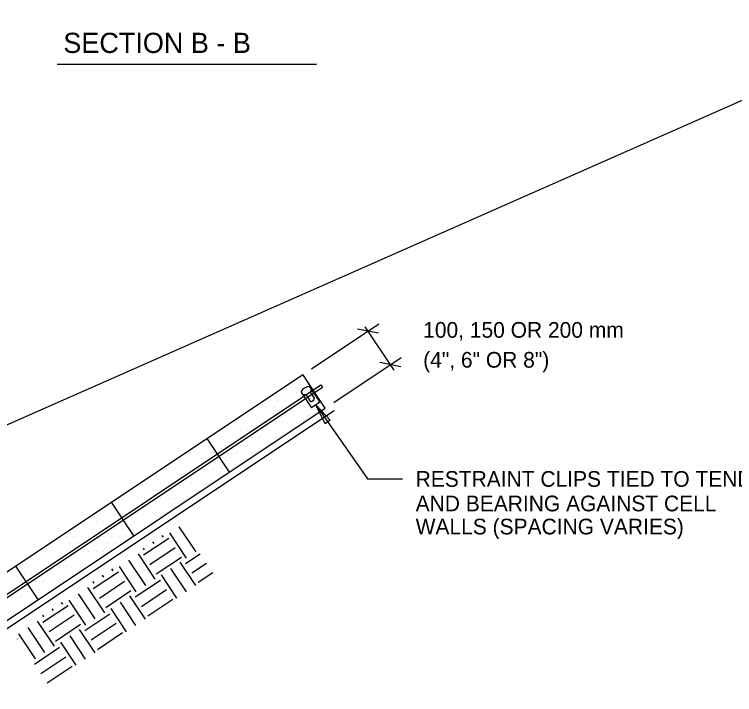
# Model space of a CAD drawing. Extents: x 638850 to 644908, y 297188 to 298900.
# Drawn here: x 641716.6 to 641845.1, y 297497.1 to 297618.5 of the extents above; entities that cross this region are included whole.
import ezdxf

# ---------------------------------------------------------------- set-up
doc = ezdxf.new("R2010")
doc.units = 0
for name, color, linetype in [('1', 7, 'Continuous'), ('12', 7, 'Continuous'), ('13', 7, 'Continuous'), ('3', 7, 'Continuous'), ('4', 7, 'Continuous'), ('5', 7, 'Continuous'), ('6', 7, 'Continuous'), ('7', 7, 'Continuous'), ('8', 7, 'Continuous')]:
    doc.layers.add(name, color=color, linetype=linetype)

msp = doc.modelspace()

# ---------------------------------------------------------------- linework, layer by layer
at = {"layer": '1'}
msp.add_line((644544.42, 298794.06), (640943.9, 297204.77), dxfattribs=at)
at = {"layer": '12'}
for p, q in [((641768.33, 297553.73), (641768.33, 297553.73)), ((641766.31, 297552.38), (641766.31, 297552.38)), ((641767.66, 297552.38), (641767.66, 297552.38)), ((641769.01, 297552.38), (641769.01, 297552.38)), ((641764.28, 297551.03), (641764.28, 297551.03)), ((641765.63, 297551.03), (641765.63, 297551.03)), ((641766.98, 297551.03), (641766.98, 297551.03)), ((641768.33, 297551.03), (641768.33, 297551.03)), ((641769.68, 297551.03), (641769.68, 297551.03)), ((641762.26, 297549.68), (641762.26, 297549.68)), ((641763.61, 297549.68), (641763.61, 297549.68)), ((641764.96, 297549.68), (641764.96, 297549.68)), ((641766.31, 297549.68), (641766.31, 297549.68)), ((641767.66, 297549.68), (641767.66, 297549.68)), ((641769.01, 297549.68), (641769.01, 297549.68)), ((641770.36, 297549.68), (641770.36, 297549.68)), ((641760.23, 297548.33), (641760.23, 297548.33)), ((641761.58, 297548.33), (641761.58, 297548.33)), ((641762.93, 297548.33), (641762.93, 297548.33)), ((641764.28, 297548.33), (641764.28, 297548.33)), ((641765.63, 297548.33), (641765.63, 297548.33)), ((641766.98, 297548.33), (641766.98, 297548.33)), ((641768.33, 297548.33), (641768.33, 297548.33)), ((641769.68, 297548.33), (641769.68, 297548.33)), ((641771.03, 297548.33), (641771.03, 297548.33)), ((641758.21, 297546.98), (641758.21, 297546.98)), ((641759.56, 297546.98), (641759.56, 297546.98)), ((641760.91, 297546.98), (641760.91, 297546.98)), ((641762.26, 297546.98), (641762.26, 297546.98)), ((641763.61, 297546.98), (641763.61, 297546.98)), ((641764.96, 297546.98), (641764.96, 297546.98)), ((641766.31, 297546.98), (641766.31, 297546.98)), ((641767.66, 297546.98), (641767.66, 297546.98)), ((641769.01, 297546.98), (641769.01, 297546.98)), ((641756.18, 297545.63), (641756.18, 297545.63)), ((641757.53, 297545.63), (641757.53, 297545.63)), ((641758.88, 297545.63), (641758.88, 297545.63)), ((641760.23, 297545.63), (641760.23, 297545.63)), ((641761.58, 297545.63), (641761.58, 297545.63)), ((641762.93, 297545.63), (641762.93, 297545.63)), ((641764.28, 297545.63), (641764.28, 297545.63)), ((641765.63, 297545.63), (641765.63, 297545.63)), ((641766.98, 297545.63), (641766.98, 297545.63)), ((641754.16, 297544.28), (641754.16, 297544.28)), ((641755.51, 297544.28), (641755.51, 297544.28)), ((641756.86, 297544.28), (641756.86, 297544.28)), ((641758.21, 297544.28), (641758.21, 297544.28)), ((641759.56, 297544.28), (641759.56, 297544.28)), ((641760.91, 297544.28), (641760.91, 297544.28)), ((641762.26, 297544.28), (641762.26, 297544.28)), ((641763.61, 297544.28), (641763.61, 297544.28)), ((641764.96, 297544.28), (641764.96, 297544.28)), ((641752.13, 297542.93), (641752.13, 297542.93)), ((641753.48, 297542.93), (641753.48, 297542.93)), ((641754.83, 297542.93), (641754.83, 297542.93)), ((641756.18, 297542.93), (641756.18, 297542.93)), ((641757.53, 297542.93), (641757.53, 297542.93)), ((641758.88, 297542.93), (641758.88, 297542.93)), ((641760.23, 297542.93), (641760.23, 297542.93)), ((641761.58, 297542.93), (641761.58, 297542.93)), ((641762.93, 297542.93), (641762.93, 297542.93)), ((641750.11, 297541.58), (641750.11, 297541.58)), ((641751.46, 297541.58), (641751.46, 297541.58)), ((641752.81, 297541.58), (641752.81, 297541.58)), ((641754.16, 297541.58), (641754.16, 297541.58)), ((641755.51, 297541.58), (641755.51, 297541.58)), ((641756.86, 297541.58), (641756.86, 297541.58)), ((641758.21, 297541.58), (641758.21, 297541.58)), ((641759.56, 297541.58), (641759.56, 297541.58)), ((641760.91, 297541.58), (641760.91, 297541.58)), ((641748.08, 297540.23), (641748.08, 297540.23)), ((641749.43, 297540.23), (641749.43, 297540.23)), ((641750.78, 297540.23), (641750.78, 297540.23)), ((641752.13, 297540.23), (641752.13, 297540.23)), ((641753.48, 297540.23), (641753.48, 297540.23)), ((641754.83, 297540.23), (641754.83, 297540.23)), ((641756.18, 297540.23), (641756.18, 297540.23)), ((641757.53, 297540.23), (641757.53, 297540.23)), ((641758.88, 297540.23), (641758.88, 297540.23)), ((641746.06, 297538.88), (641746.06, 297538.88)), ((641747.41, 297538.88), (641747.41, 297538.88)), ((641748.76, 297538.88), (641748.76, 297538.88)), ((641750.11, 297538.88), (641750.11, 297538.88)), ((641751.46, 297538.88), (641751.46, 297538.88)), ((641752.81, 297538.88), (641752.81, 297538.88)), ((641754.16, 297538.88), (641754.16, 297538.88)), ((641755.51, 297538.88), (641755.51, 297538.88)), ((641756.86, 297538.88), (641756.86, 297538.88)), ((641744.03, 297537.53), (641744.03, 297537.53)), ((641745.38, 297537.53), (641745.38, 297537.53)), ((641746.73, 297537.53), (641746.73, 297537.53)), ((641748.08, 297537.53), (641748.08, 297537.53)), ((641749.43, 297537.53), (641749.43, 297537.53)), ((641750.78, 297537.53), (641750.78, 297537.53)), ((641752.13, 297537.53), (641752.13, 297537.53)), ((641753.48, 297537.53), (641753.48, 297537.53)), ((641754.83, 297537.53), (641754.83, 297537.53)), ((641742.01, 297536.18), (641742.01, 297536.18)), ((641743.36, 297536.18), (641743.36, 297536.18)), ((641744.71, 297536.18), (641744.71, 297536.18)), ((641746.06, 297536.18), (641746.06, 297536.18)), ((641747.41, 297536.18), (641747.41, 297536.18)), ((641748.76, 297536.18), (641748.76, 297536.18)), ((641750.11, 297536.18), (641750.11, 297536.18)), ((641751.46, 297536.18), (641751.46, 297536.18)), ((641752.81, 297536.18), (641752.81, 297536.18)), ((641739.98, 297534.83), (641739.98, 297534.83)), ((641741.33, 297534.83), (641741.33, 297534.83)), ((641742.68, 297534.83), (641742.68, 297534.83)), ((641744.03, 297534.83), (641744.03, 297534.83)), ((641745.38, 297534.83), (641745.38, 297534.83)), ((641746.73, 297534.83), (641746.73, 297534.83)), ((641748.08, 297534.83), (641748.08, 297534.83)), ((641749.43, 297534.83), (641749.43, 297534.83)), ((641750.78, 297534.83), (641750.78, 297534.83)), ((641737.96, 297533.48), (641737.96, 297533.48)), ((641739.31, 297533.48), (641739.31, 297533.48)), ((641740.66, 297533.48), (641740.66, 297533.48)), ((641742.01, 297533.48), (641742.01, 297533.48)), ((641743.36, 297533.48), (641743.36, 297533.48)), ((641744.71, 297533.48), (641744.71, 297533.48)), ((641746.06, 297533.48), (641746.06, 297533.48)), ((641747.41, 297533.48), (641747.41, 297533.48)), ((641748.76, 297533.48), (641748.76, 297533.48)), ((641735.93, 297532.13), (641735.93, 297532.13)), ((641737.28, 297532.13), (641737.28, 297532.13)), ((641738.63, 297532.13), (641738.63, 297532.13)), ((641739.98, 297532.13), (641739.98, 297532.13)), ((641741.33, 297532.13), (641741.33, 297532.13)), ((641742.68, 297532.13), (641742.68, 297532.13)), ((641744.03, 297532.13), (641744.03, 297532.13)), ((641745.38, 297532.13), (641745.38, 297532.13)), ((641746.73, 297532.13), (641746.73, 297532.13)), ((641733.91, 297530.78), (641733.91, 297530.78)), ((641735.26, 297530.78), (641735.26, 297530.78)), ((641736.61, 297530.78), (641736.61, 297530.78)), ((641737.96, 297530.78), (641737.96, 297530.78)), ((641739.31, 297530.78), (641739.31, 297530.78)), ((641740.66, 297530.78), (641740.66, 297530.78)), ((641742.01, 297530.78), (641742.01, 297530.78)), ((641743.36, 297530.78), (641743.36, 297530.78)), ((641744.71, 297530.78), (641744.71, 297530.78)), ((641731.88, 297529.43), (641731.88, 297529.43)), ((641733.23, 297529.43), (641733.23, 297529.43)), ((641734.58, 297529.43), (641734.58, 297529.43)), ((641735.93, 297529.43), (641735.93, 297529.43)), ((641737.28, 297529.43), (641737.28, 297529.43)), ((641738.63, 297529.43), (641738.63, 297529.43)), ((641739.98, 297529.43), (641739.98, 297529.43)), ((641741.33, 297529.43), (641741.33, 297529.43)), ((641742.68, 297529.43), (641742.68, 297529.43)), ((641729.86, 297528.08), (641729.86, 297528.08)), ((641731.21, 297528.08), (641731.21, 297528.08)), ((641732.56, 297528.08), (641732.56, 297528.08)), ((641733.91, 297528.08), (641733.91, 297528.08)), ((641735.26, 297528.08), (641735.26, 297528.08)), ((641736.61, 297528.08), (641736.61, 297528.08)), ((641737.96, 297528.08), (641737.96, 297528.08)), ((641739.31, 297528.08), (641739.31, 297528.08)), ((641740.66, 297528.08), (641740.66, 297528.08)), ((641727.83, 297526.73), (641727.83, 297526.73)), ((641729.18, 297526.73), (641729.18, 297526.73)), ((641730.53, 297526.73), (641730.53, 297526.73)), ((641731.88, 297526.73), (641731.88, 297526.73)), ((641733.23, 297526.73), (641733.23, 297526.73)), ((641734.58, 297526.73), (641734.58, 297526.73)), ((641735.93, 297526.73), (641735.93, 297526.73)), ((641737.28, 297526.73), (641737.28, 297526.73)), ((641738.63, 297526.73), (641738.63, 297526.73)), ((641725.81, 297525.38), (641725.81, 297525.38)), ((641727.16, 297525.38), (641727.16, 297525.38)), ((641728.51, 297525.38), (641728.51, 297525.38)), ((641729.86, 297525.38), (641729.86, 297525.38)), ((641731.21, 297525.38), (641731.21, 297525.38)), ((641732.56, 297525.38), (641732.56, 297525.38)), ((641733.91, 297525.38), (641733.91, 297525.38)), ((641735.26, 297525.38), (641735.26, 297525.38)), ((641736.61, 297525.38), (641736.61, 297525.38)), ((641723.78, 297524.03), (641723.78, 297524.03)), ((641725.13, 297524.03), (641725.13, 297524.03)), ((641726.48, 297524.03), (641726.48, 297524.03)), ((641727.83, 297524.03), (641727.83, 297524.03)), ((641729.18, 297524.03), (641729.18, 297524.03)), ((641730.53, 297524.03), (641730.53, 297524.03)), ((641731.88, 297524.03), (641731.88, 297524.03)), ((641733.23, 297524.03), (641733.23, 297524.03)), ((641734.58, 297524.03), (641734.58, 297524.03)), ((641721.76, 297522.68), (641721.76, 297522.68)), ((641723.11, 297522.68), (641723.11, 297522.68)), ((641724.46, 297522.68), (641724.46, 297522.68)), ((641725.81, 297522.68), (641725.81, 297522.68)), ((641727.16, 297522.68), (641727.16, 297522.68)), ((641728.51, 297522.68), (641728.51, 297522.68)), ((641729.86, 297522.68), (641729.86, 297522.68)), ((641731.21, 297522.68), (641731.21, 297522.68)), ((641732.56, 297522.68), (641732.56, 297522.68)), ((641719.73, 297521.33), (641719.73, 297521.33)), ((641721.08, 297521.33), (641721.08, 297521.33)), ((641722.43, 297521.33), (641722.43, 297521.33)), ((641723.78, 297521.33), (641723.78, 297521.33)), ((641725.13, 297521.33), (641725.13, 297521.33)), ((641726.48, 297521.33), (641726.48, 297521.33)), ((641727.83, 297521.33), (641727.83, 297521.33)), ((641729.18, 297521.33), (641729.18, 297521.33)), ((641730.53, 297521.33), (641730.53, 297521.33)), ((641717.71, 297519.98), (641717.71, 297519.98)), ((641719.06, 297519.98), (641719.06, 297519.98)), ((641720.41, 297519.98), (641720.41, 297519.98)), ((641721.76, 297519.98), (641721.76, 297519.98)), ((641723.11, 297519.98), (641723.11, 297519.98)), ((641724.46, 297519.98), (641724.46, 297519.98)), ((641725.81, 297519.98), (641725.81, 297519.98)), ((641727.16, 297519.98), (641727.16, 297519.98)), ((641728.51, 297519.98), (641728.51, 297519.98)), ((641717.03, 297518.63), (641717.03, 297518.63)), ((641718.38, 297518.63), (641718.38, 297518.63)), ((641719.73, 297518.63), (641719.73, 297518.63)), ((641721.08, 297518.63), (641721.08, 297518.63)), ((641722.43, 297518.63), (641722.43, 297518.63)), ((641723.78, 297518.63), (641723.78, 297518.63)), ((641725.13, 297518.63), (641725.13, 297518.63)), ((641726.48, 297518.63), (641726.48, 297518.63)), ((641717.71, 297517.28), (641717.71, 297517.28)), ((641719.06, 297517.28), (641719.06, 297517.28)), ((641720.41, 297517.28), (641720.41, 297517.28)), ((641721.76, 297517.28), (641721.76, 297517.28)), ((641723.11, 297517.28), (641723.11, 297517.28)), ((641724.46, 297517.28), (641724.46, 297517.28)), ((641717.03, 297515.93), (641717.03, 297515.93)), ((641718.38, 297515.93), (641718.38, 297515.93)), ((641719.73, 297515.93), (641719.73, 297515.93)), ((641721.08, 297515.93), (641721.08, 297515.93)), ((641722.43, 297515.93), (641722.43, 297515.93)), ((641717.71, 297514.58), (641717.71, 297514.58)), ((641719.06, 297514.58), (641719.06, 297514.58)), ((641720.41, 297514.58), (641720.41, 297514.58)), ((641717.03, 297513.23), (641717.03, 297513.23)), ((641718.38, 297513.23), (641718.38, 297513.23))]:
    msp.add_line(p, q, dxfattribs=at)
at = {"layer": '13'}
for p, q in [((641747.31, 297521.47), (641744.31, 297525.96)), ((641748.99, 297522.59), (641746, 297527.08)), ((641739.63, 297522.03), (641744.13, 297525.02)), ((641743.19, 297525.21), (641742.98, 297525.52)), ((641739.82, 297522.96), (641739.61, 297523.27)), ((641740.76, 297520.34), (641745.25, 297523.34)), ((641741.5, 297524.09), (641741.3, 297524.4)), ((641741.7, 297517.72), (641738.7, 297522.22)), ((641747.12, 297520.53), (641749.71, 297522.26)), ((641740.01, 297516.6), (641737.01, 297521.09)), ((641741.88, 297518.66), (641746.37, 297521.65)), ((641748.95, 297516.57), (641746.19, 297520.72)), ((641734.21, 297519.22), (641734, 297519.53)), ((641738.33, 297515.47), (641735.33, 297519.97)), ((641747.27, 297515.45), (641744.5, 297519.6)), ((641748.25, 297518.85), (641750.83, 297520.57)), ((641730.65, 297516.04), (641735.14, 297519.03)), ((641732.52, 297518.09), (641732.31, 297518.4)), ((641745.58, 297514.33), (641742.82, 297518.47)), ((641749.37, 297517.16), (641751.96, 297518.89)), ((641730.84, 297516.97), (641730.63, 297517.28)), ((641731.77, 297514.35), (641736.26, 297517.35)), ((641738.14, 297514.54), (641742.63, 297517.54)), ((641732.71, 297511.73), (641729.71, 297516.22)), ((641732.9, 297512.67), (641737.39, 297515.66)), ((641739.26, 297512.85), (641743.75, 297515.85)), ((641731.02, 297510.61), (641728.03, 297515.1)), ((641739.97, 297510.58), (641737.2, 297514.73)), ((641721.66, 297510.04), (641726.16, 297513.04)), ((641725.22, 297513.23), (641725.02, 297513.53)), ((641729.34, 297509.48), (641726.34, 297513.98)), ((641738.28, 297509.46), (641735.52, 297513.6)), ((641740.38, 297511.17), (641744.88, 297514.17)), ((641723.54, 297512.1), (641723.33, 297512.41)), ((641736.6, 297508.33), (641733.83, 297512.48)), ((641721.85, 297510.98), (641721.65, 297511.29)), ((641722.79, 297508.36), (641727.28, 297511.36)), ((641729.15, 297508.55), (641733.64, 297511.54)), ((641723.72, 297505.74), (641720.73, 297510.23)), ((641723.91, 297506.67), (641728.4, 297509.67)), ((641730.28, 297506.86), (641734.77, 297509.86)), ((641720.35, 297503.49), (641717.36, 297507.98)), ((641722.04, 297504.61), (641719.04, 297509.11)), ((641730.98, 297504.59), (641728.22, 297508.73)), ((641731.4, 297505.18), (641735.89, 297508.17)), ((641717.13, 297507.02), (641717.17, 297507.05)), ((641729.3, 297503.46), (641726.53, 297507.61)), ((641718.25, 297505.34), (641718.3, 297505.36)), ((641720.17, 297502.56), (641724.66, 297505.55)), ((641727.61, 297502.34), (641724.85, 297506.49)), ((641719.38, 297503.65), (641719.42, 297503.68)), ((641721.29, 297500.87), (641725.78, 297503.87)), ((641722.41, 297499.19), (641726.91, 297502.18))]:
    msp.add_line(p, q, dxfattribs=at)
at = {"layer": '3'}
msp.add_line((641724.23, 297609.62), (641770.51, 297609.62), dxfattribs=at)
at = {"layer": '4'}
msp.add_lwpolyline([(641650.39, 297471.74), (641771.27, 297552.37), (641771.57, 297551.92), (641650.69, 297471.29)], close=True, dxfattribs=at)
at = {"layer": '5'}
for p, q in [((641648.54, 297474.51), (641768.04, 297554.21)), ((641772.03, 297548.22), (641768.04, 297554.21)), ((641652.53, 297468.52), (641772.03, 297548.22)), ((641770.34, 297548.8), (641779.55, 297535.59)), ((641754.96, 297536.83), (641750.97, 297542.82)), ((641779.55, 297535.59), (641785.85, 297535.59)), ((641737.89, 297525.45), (641733.9, 297531.44)), ((641720.82, 297514.06), (641716.82, 297520.05))]:
    msp.add_line(p, q, dxfattribs=at)
msp.add_lwpolyline([(641772.02, 297545.44), (641770.34, 297548.8), (641772.91, 297546.06)], close=True, dxfattribs=at)
at = {"layer": '6'}
for p, q in [((641769.6, 297555.25), (641781.61, 297563.26)), ((641781.55, 297561.59), (641777.8, 297562.34)), ((641784.31, 297555.01), (641779.14, 297562.77)), ((641773.6, 297549.26), (641785.61, 297557.27)), ((641785.54, 297555.61), (641781.79, 297556.35))]:
    msp.add_line(p, q, dxfattribs=at)
at = {"layer": '7'}
for p, q in [((641769.25, 297552.06), (641771.09, 297549.3)), ((641767.75, 297551.06), (641769.6, 297548.3)), ((641768.12, 297550.53), (641768.11, 297550.53)), ((641768.74, 297550.41), (641769.34, 297549.5)), ((641769.48, 297550.9), (641770.08, 297550)), ((641769.61, 297551.53), (641769.6, 297551.53)), ((641771.09, 297549.3), (641769.6, 297548.3)), ((641769.65, 297549.44), (641770.02, 297549.69))]:
    msp.add_line(p, q, dxfattribs=at)
for centre, radius, start, end in [((641769.4, 297550.22), 1.91, 97.7555, 149.6445), ((641769.16, 297552), 0.112, 33.6995, 97.7554), ((641767.85, 297551.13), 0.112, 149.6441, 213.7), ((641768.37, 297550.16), 0.45, 33.7, 123.7), ((641769.85, 297551.15), 0.45, 123.7, 213.7), ((641769.53, 297549.63), 0.225, 213.7, 303.7), ((641769.9, 297549.87), 0.225, 303.7, 33.7)]:
    msp.add_arc(centre, radius, start, end, dxfattribs=at)
at = {"layer": '8'}
msp.add_line((641653.12, 297467.47), (641773.63, 297547.84), dxfattribs=at)

# ---------------------------------------------------------------- texts
at = {"layer": '3'}
for s, height, p in [('SECTION B - B', 3.6022, (641725.32, 297611.62)), ('100, 150 OR 200 mm', 2.799, (641789.51, 297560.8)), ('(4", 6" OR 8")', 2.799, (641789.51, 297555.46)), ('RESTRAINT CLIPS TIED TO TENDONS', 2.7991, (641788.17, 297534.2)), ('AND BEARING AGAINST CELL', 2.7991, (641788.17, 297529.82)), ('WALLS (SPACING VARIES)', 2.7991, (641788.17, 297525.7))]:
    msp.add_text(s, height=height, dxfattribs=at).set_placement(p)

doc.saveas('drawing.dxf')
